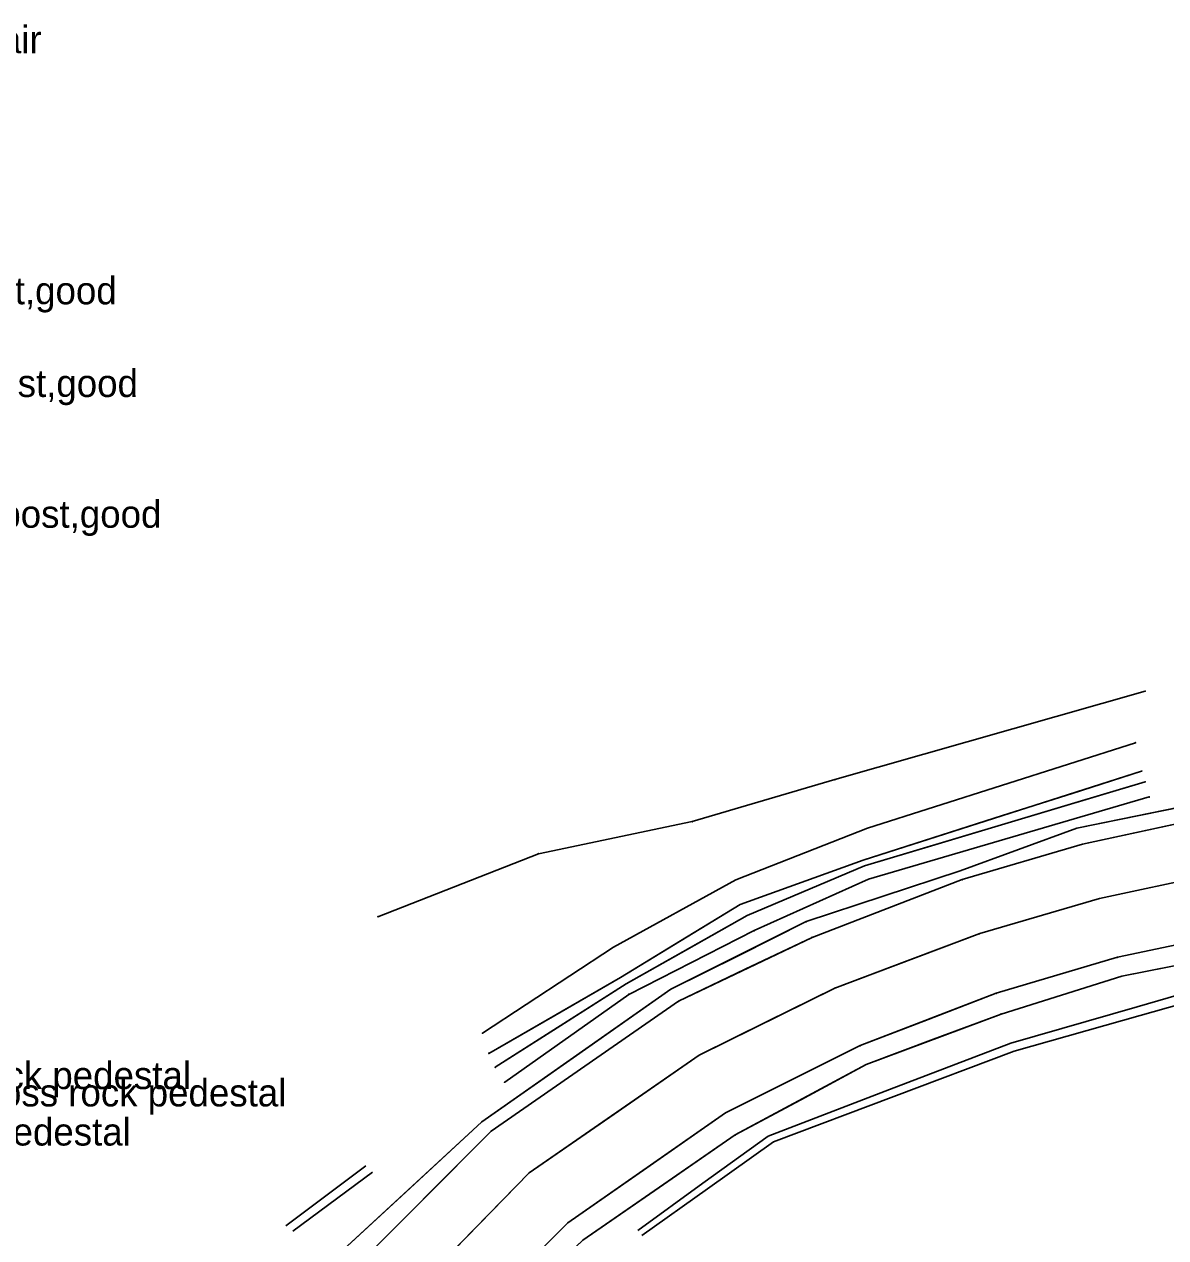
# Model space of a CAD drawing. Extents: x -99999 to 591807, y -99999 to 347168.
# Drawn here: x 591264.4 to 591472.6, y 321587.5 to 321808.7 of the extents above; entities that cross this region are included whole.
import ezdxf

# ---------------------------------------------------------------- set-up
doc = ezdxf.new("R2010")
doc.units = 0
for name, color, linetype in [('S_BREAKLINE', 7, 'Continuous'), ('S_DITCHLINE', 7, 'Continuous'), ('S_EDGE_PAVEMENT', 7, 'Continuous'), ('S_FENCE_ANNOT', 7, 'Continuous'), ('S_GRD_PT_SYM', 7, 'Continuous'), ('S_PAVEMENT_CROWN', 7, 'Continuous'), ('S_RDW_PT_SYM', 7, 'Continuous'), ('S_SHOULDER', 7, 'Continuous'), ('S_SURVEY_TEXT_ANNOT', 7, 'Continuous')]:
    doc.layers.add(name, color=color, linetype=linetype)

msp = doc.modelspace()

# ---------------------------------------------------------------- linework, layer by layer
at = {"layer": 'S_BREAKLINE'}
for points in [[(591468.8, 321687.13), (591412.23, 321671), (591386.24, 321663.34), (591358.18, 321657.49), (591328.93, 321646.02)], [(591467.04, 321677.72), (591418.2, 321662.17), (591394.18, 321652.72), (591371.88, 321640.46), (591348, 321624.79)], [(591469.54, 321667.85), (591418.4, 321652.88), (591397.51, 321643.48), (591374.67, 321631.86), (591352.04, 321615.87)]]:
    msp.add_lwpolyline(points, dxfattribs=at)
at = {"layer": 'S_DITCHLINE'}
for points in [[(591468.17, 321672.55), (591417.4, 321656.34), (591394.97, 321648.25), (591373.17, 321634.92), (591349.14, 321621.11)], [(591468.17, 321672.55), (591455.48, 321668.5), (591442.78, 321664.44), (591430.09, 321660.39), (591417.4, 321656.34), (591394.97, 321648.25), (591384.07, 321641.59), (591373.17, 321634.92), (591361.15, 321628.02), (591349.14, 321621.11)], [(591468.8, 321670.6), (591417.66, 321655.29), (591396.22, 321646.24), (591374.16, 321633.77), (591350.33, 321618.57)], [(591468.8, 321670.6), (591456.01, 321666.78), (591443.23, 321662.95), (591430.44, 321659.12), (591417.66, 321655.29), (591396.22, 321646.24), (591385.19, 321640), (591374.16, 321633.77), (591362.25, 321626.17), (591350.33, 321618.57)], [(591620.59, 321648.39), (591601.9, 321647.32), (591583.22, 321646.25), (591564.54, 321645.18), (591545.85, 321644.11), (591531.99, 321642.15), (591518.12, 321640.19), (591504.25, 321638.23), (591490.39, 321636.27), (591467.34, 321629.61), (591444.3, 321622.96), (591422.18, 321614.5), (591400.07, 321606.03), (591388.18, 321597.43), (591376.3, 321588.82)], [(591605.48, 321641.57), (591590.53, 321641.68), (591575.58, 321641.79), (591560.63, 321641.91), (591545.68, 321642.02), (591532, 321640.14), (591518.31, 321638.26), (591504.63, 321636.38), (591490.94, 321634.5), (591467.93, 321628.01), (591444.92, 321621.52), (591422.97, 321613.24), (591401.03, 321604.97), (591389.04, 321596.44), (591377.05, 321587.9)], [(591312.11, 321589.68), (591326.71, 321600.59)], [(591313.38, 321588.7), (591327.91, 321599.47)]]:
    msp.add_lwpolyline(points, dxfattribs=at)
at = {"layer": 'S_EDGE_PAVEMENT'}
for points in [[(591265.83, 321431.03), (591274.57, 321469.53), (591285.68, 321510.83), (591303.4, 321551.75), (591324.73, 321582.05), (591349.57, 321606.91), (591383.71, 321630.61), (591408.09, 321642.24), (591435.47, 321652.78), (591457.41, 321659.24), (591499.52, 321668.33), (591535.47, 321673.26), (591580.66, 321677.52), (591617.82, 321679.86), (591660.43, 321681.8), (591716.05, 321683.42)], [(591265.83, 321431.03), (591270.2, 321450.28), (591274.57, 321469.53), (591280.13, 321490.18), (591285.68, 321510.83), (591294.54, 321531.29), (591303.4, 321551.75), (591314.06, 321566.9), (591324.73, 321582.05), (591337.15, 321594.48), (591349.57, 321606.91), (591366.64, 321618.76), (591383.71, 321630.61), (591395.9, 321636.43), (591408.09, 321642.24), (591421.78, 321647.51), (591435.47, 321652.78), (591457.41, 321659.24), (591478.46, 321663.78)], [(591284.27, 321341.23), (591285.36, 321368.86), (591287.64, 321404.72), (591289.71, 321427.44), (591295.82, 321464.74), (591306.84, 321503.71), (591322.94, 321541.59), (591339.23, 321566.07), (591363.58, 321590.23), (591392.3, 321610.26), (591416.84, 321622.53), (591441.66, 321632.07), (591463.77, 321638.62), (591501.91, 321646.69), (591536.38, 321651.55), (591579.84, 321655.46), (591619.52, 321658.01), (591661.35, 321660.14), (591715.94, 321661.78)], [(591284.27, 321341.23), (591284.81, 321355.05), (591285.36, 321368.86), (591286.5, 321386.79), (591287.64, 321404.72), (591289.71, 321427.44), (591292.77, 321446.09), (591295.82, 321464.74), (591301.33, 321484.23), (591306.84, 321503.71), (591314.89, 321522.65), (591322.94, 321541.59), (591331.09, 321553.83), (591339.23, 321566.07), (591351.4, 321578.15), (591363.58, 321590.23), (591377.94, 321600.25), (591392.3, 321610.26), (591404.57, 321616.39), (591416.84, 321622.53), (591429.25, 321627.3), (591441.66, 321632.07), (591463.77, 321638.62), (591482.84, 321642.65)]]:
    msp.add_lwpolyline(points, dxfattribs=at)
at = {"layer": 'S_GRD_PT_SYM'}
for points in [[(591468.8, 321687.13), (591468.81, 321687.08), (591468.8, 321687.13), (591468.85, 321687.14), (591468.8, 321687.13), (591468.79, 321687.18), (591468.8, 321687.13), (591468.75, 321687.12)], [(591467.04, 321677.72), (591467.06, 321677.67), (591467.04, 321677.72), (591467.09, 321677.74), (591467.04, 321677.72), (591467.03, 321677.77), (591467.04, 321677.72), (591467, 321677.71)], [(591468.17, 321672.55), (591468.19, 321672.5), (591468.17, 321672.55), (591468.22, 321672.56), (591468.17, 321672.55), (591468.15, 321672.6), (591468.17, 321672.55), (591468.12, 321672.53)], [(591412.23, 321671), (591412.25, 321670.95), (591412.23, 321671), (591412.28, 321671.01), (591412.23, 321671), (591412.22, 321671.04), (591412.23, 321671), (591412.18, 321670.98)], [(591468.8, 321670.6), (591468.81, 321670.55), (591468.8, 321670.6), (591468.85, 321670.62), (591468.8, 321670.6), (591468.78, 321670.65), (591468.8, 321670.6), (591468.75, 321670.59)], [(591469.54, 321667.85), (591469.56, 321667.8), (591469.54, 321667.85), (591469.59, 321667.86), (591469.54, 321667.85), (591469.53, 321667.9), (591469.54, 321667.85), (591469.49, 321667.83)], [(591386.24, 321663.34), (591386.25, 321663.29), (591386.24, 321663.34), (591386.29, 321663.35), (591386.24, 321663.34), (591386.23, 321663.39), (591386.24, 321663.34), (591386.19, 321663.33)], [(591418.2, 321662.17), (591418.22, 321662.12), (591418.2, 321662.17), (591418.25, 321662.19), (591418.2, 321662.17), (591418.18, 321662.21), (591418.2, 321662.17), (591418.15, 321662.15)], [(591358.18, 321657.49), (591358.2, 321657.45), (591358.18, 321657.49), (591358.23, 321657.51), (591358.18, 321657.49), (591358.16, 321657.54), (591358.18, 321657.49), (591358.14, 321657.47)], [(591417.4, 321656.34), (591417.41, 321656.29), (591417.4, 321656.34), (591417.44, 321656.35), (591417.4, 321656.34), (591417.38, 321656.38), (591417.4, 321656.34), (591417.35, 321656.32)], [(591417.66, 321655.29), (591417.68, 321655.25), (591417.66, 321655.29), (591417.7, 321655.31), (591417.66, 321655.29), (591417.64, 321655.34), (591417.66, 321655.29), (591417.61, 321655.27)], [(591394.18, 321652.72), (591394.21, 321652.68), (591394.18, 321652.72), (591394.23, 321652.75), (591394.18, 321652.72), (591394.16, 321652.77), (591394.18, 321652.72), (591394.14, 321652.7)], [(591418.4, 321652.88), (591418.42, 321652.83), (591418.4, 321652.88), (591418.44, 321652.9), (591418.4, 321652.88), (591418.37, 321652.92), (591418.4, 321652.88), (591418.35, 321652.86)], [(591394.97, 321648.25), (591395, 321648.21), (591394.97, 321648.25), (591395.02, 321648.28), (591394.97, 321648.25), (591394.95, 321648.3), (591394.97, 321648.25), (591394.93, 321648.23)], [(591328.93, 321646.02), (591328.95, 321645.97), (591328.93, 321646.02), (591328.98, 321646.03), (591328.93, 321646.02), (591328.92, 321646.06), (591328.93, 321646.02), (591328.89, 321646)], [(591396.22, 321646.24), (591396.24, 321646.2), (591396.22, 321646.24), (591396.26, 321646.26), (591396.22, 321646.24), (591396.19, 321646.28), (591396.22, 321646.24), (591396.17, 321646.21)], [(591397.51, 321643.48), (591397.53, 321643.43), (591397.51, 321643.48), (591397.55, 321643.5), (591397.51, 321643.48), (591397.49, 321643.52), (591397.51, 321643.48), (591397.46, 321643.45)], [(591371.88, 321640.46), (591371.9, 321640.41), (591371.88, 321640.46), (591371.92, 321640.48), (591371.88, 321640.46), (591371.85, 321640.5), (591371.88, 321640.46), (591371.83, 321640.43)], [(591373.17, 321634.92), (591373.2, 321634.88), (591373.17, 321634.92), (591373.21, 321634.95), (591373.17, 321634.92), (591373.15, 321634.97), (591373.17, 321634.92), (591373.13, 321634.9)], [(591374.16, 321633.77), (591374.19, 321633.73), (591374.16, 321633.77), (591374.2, 321633.8), (591374.16, 321633.77), (591374.13, 321633.81), (591374.16, 321633.77), (591374.12, 321633.74)], [(591374.67, 321631.86), (591374.7, 321631.82), (591374.67, 321631.86), (591374.71, 321631.88), (591374.67, 321631.86), (591374.64, 321631.9), (591374.67, 321631.86), (591374.63, 321631.83)], [(591348, 321624.79), (591348.03, 321624.75), (591348, 321624.79), (591348.04, 321624.82), (591348, 321624.79), (591347.97, 321624.83), (591348, 321624.79), (591347.96, 321624.76)], [(591349.14, 321621.11), (591349.16, 321621.07), (591349.14, 321621.11), (591349.18, 321621.14), (591349.14, 321621.11), (591349.11, 321621.15), (591349.14, 321621.11), (591349.1, 321621.09)], [(591350.33, 321618.57), (591350.36, 321618.52), (591350.33, 321618.57), (591350.37, 321618.59), (591350.33, 321618.57), (591350.31, 321618.61), (591350.33, 321618.57), (591350.29, 321618.54)], [(591352.04, 321615.87), (591352.07, 321615.82), (591352.04, 321615.87), (591352.08, 321615.89), (591352.04, 321615.87), (591352.01, 321615.91), (591352.04, 321615.87), (591352, 321615.84)]]:
    msp.add_lwpolyline(points, close=True, dxfattribs=at)
at = {"layer": 'S_PAVEMENT_CROWN'}
for points in [[(591273.09, 321336.11), (591274.57, 321369.52), (591276.45, 321407.87), (591278.42, 321428.53), (591284.72, 321467.31), (591295.64, 321507.96), (591312.94, 321546.95), (591329.16, 321571.32), (591356.48, 321599.33), (591387.51, 321620.77), (591412.26, 321633.01), (591438.64, 321642.94), (591460.49, 321649.34), (591500.26, 321657.86), (591536.84, 321663), (591581.11, 321666.95), (591618.78, 321669.22), (591660.89, 321671.3), (591716.05, 321672.97)], [(591273.09, 321336.11), (591273.83, 321352.81), (591274.57, 321369.52), (591275.51, 321388.69), (591276.45, 321407.87), (591278.42, 321428.53), (591281.57, 321447.92), (591284.72, 321467.31), (591290.18, 321487.63), (591295.64, 321507.96), (591304.29, 321527.45), (591312.94, 321546.95), (591321.05, 321559.13), (591329.16, 321571.32), (591342.82, 321585.32), (591356.48, 321599.33), (591372, 321610.05), (591387.51, 321620.77), (591399.89, 321626.89), (591412.26, 321633.01), (591425.45, 321637.98), (591438.64, 321642.94), (591460.49, 321649.34), (591480.37, 321653.6)]]:
    msp.add_lwpolyline(points, dxfattribs=at)
at = {"layer": 'S_RDW_PT_SYM'}
for points in [[(591456.36, 321662.16), (591456.35, 321662.21), (591456.36, 321662.16), (591456.31, 321662.15), (591456.36, 321662.16), (591456.37, 321662.11), (591456.36, 321662.16), (591456.41, 321662.17)], [(591457.41, 321659.24), (591457.4, 321659.28), (591457.41, 321659.24), (591457.36, 321659.23), (591457.41, 321659.24), (591457.42, 321659.19), (591457.41, 321659.24), (591457.46, 321659.25)], [(591435.07, 321654.38), (591435.05, 321654.43), (591435.07, 321654.38), (591435.02, 321654.37), (591435.07, 321654.38), (591435.09, 321654.34), (591435.07, 321654.38), (591435.12, 321654.4)], [(591435.47, 321652.78), (591435.45, 321652.83), (591435.47, 321652.78), (591435.42, 321652.76), (591435.47, 321652.78), (591435.48, 321652.73), (591435.47, 321652.78), (591435.52, 321652.79)], [(591460.49, 321649.34), (591460.48, 321649.38), (591460.49, 321649.34), (591460.44, 321649.32), (591460.49, 321649.34), (591460.5, 321649.29), (591460.49, 321649.34), (591460.54, 321649.35)], [(591407.03, 321645.12), (591407.01, 321645.17), (591407.03, 321645.12), (591406.98, 321645.11), (591407.03, 321645.12), (591407.05, 321645.08), (591407.03, 321645.12), (591407.08, 321645.14)], [(591408.09, 321642.24), (591408.08, 321642.29), (591408.09, 321642.24), (591408.05, 321642.23), (591408.09, 321642.24), (591408.11, 321642.2), (591408.09, 321642.24), (591408.14, 321642.26)], [(591438.64, 321642.94), (591438.63, 321642.99), (591438.64, 321642.94), (591438.6, 321642.93), (591438.64, 321642.94), (591438.66, 321642.89), (591438.64, 321642.94), (591438.69, 321642.95)], [(591463.77, 321638.62), (591463.76, 321638.67), (591463.77, 321638.62), (591463.72, 321638.61), (591463.77, 321638.62), (591463.78, 321638.57), (591463.77, 321638.62), (591463.82, 321638.63)], [(591464.57, 321635.19), (591464.56, 321635.23), (591464.57, 321635.19), (591464.52, 321635.18), (591464.57, 321635.19), (591464.58, 321635.14), (591464.57, 321635.19), (591464.62, 321635.19)], [(591382.36, 321632.81), (591382.34, 321632.85), (591382.36, 321632.81), (591382.32, 321632.79), (591382.36, 321632.81), (591382.39, 321632.76), (591382.36, 321632.81), (591382.41, 321632.83)], [(591412.26, 321633.01), (591412.24, 321633.06), (591412.26, 321633.01), (591412.21, 321633), (591412.26, 321633.01), (591412.28, 321632.97), (591412.26, 321633.01), (591412.31, 321633.03)], [(591441.66, 321632.07), (591441.64, 321632.12), (591441.66, 321632.07), (591441.61, 321632.05), (591441.66, 321632.07), (591441.67, 321632.02), (591441.66, 321632.07), (591441.71, 321632.08)], [(591383.71, 321630.61), (591383.69, 321630.65), (591383.71, 321630.61), (591383.67, 321630.59), (591383.71, 321630.61), (591383.73, 321630.56), (591383.71, 321630.61), (591383.76, 321630.63)], [(591442.53, 321628.28), (591442.52, 321628.33), (591442.53, 321628.28), (591442.49, 321628.26), (591442.53, 321628.28), (591442.55, 321628.23), (591442.53, 321628.28), (591442.58, 321628.29)], [(591416.84, 321622.53), (591416.82, 321622.57), (591416.84, 321622.53), (591416.8, 321622.51), (591416.84, 321622.53), (591416.86, 321622.48), (591416.84, 321622.53), (591416.89, 321622.55)], [(591387.51, 321620.77), (591387.49, 321620.82), (591387.51, 321620.77), (591387.47, 321620.75), (591387.51, 321620.77), (591387.53, 321620.73), (591387.51, 321620.77), (591387.56, 321620.79)], [(591417.96, 321619.1), (591417.94, 321619.14), (591417.96, 321619.1), (591417.91, 321619.08), (591417.96, 321619.1), (591417.97, 321619.05), (591417.96, 321619.1), (591418, 321619.12)], [(591392.3, 321610.26), (591392.27, 321610.31), (591392.3, 321610.26), (591392.25, 321610.24), (591392.3, 321610.26), (591392.32, 321610.22), (591392.3, 321610.26), (591392.34, 321610.28)], [(591347.89, 321608.66), (591347.87, 321608.7), (591347.89, 321608.66), (591347.85, 321608.63), (591347.89, 321608.66), (591347.92, 321608.62), (591347.89, 321608.66), (591347.94, 321608.69)], [(591349.57, 321606.91), (591349.54, 321606.96), (591349.57, 321606.91), (591349.53, 321606.89), (591349.57, 321606.91), (591349.6, 321606.87), (591349.57, 321606.91), (591349.61, 321606.94)], [(591394.06, 321606.24), (591394.04, 321606.29), (591394.06, 321606.24), (591394.02, 321606.22), (591394.06, 321606.24), (591394.09, 321606.2), (591394.06, 321606.24), (591394.11, 321606.26)], [(591356.48, 321599.33), (591356.45, 321599.37), (591356.48, 321599.33), (591356.44, 321599.3), (591356.48, 321599.33), (591356.51, 321599.29), (591356.48, 321599.33), (591356.52, 321599.36)], [(591363.58, 321590.23), (591363.55, 321590.27), (591363.58, 321590.23), (591363.53, 321590.2), (591363.58, 321590.23), (591363.6, 321590.19), (591363.58, 321590.23), (591363.62, 321590.26)]]:
    msp.add_lwpolyline(points, close=True, dxfattribs=at)
at = {"layer": 'S_SHOULDER'}
for points in [[(591264.76, 321431.46), (591270.73, 321470.65), (591281.62, 321511.98), (591300.21, 321554.03), (591321.75, 321584.49), (591347.89, 321608.66), (591382.36, 321632.81), (591407.03, 321645.12), (591435.07, 321654.38), (591456.36, 321662.16), (591499.13, 321670.85), (591534.55, 321676.66), (591580.75, 321679.7), (591617.67, 321682.67), (591660.33, 321683.79), (591716.05, 321685.24)], [(591264.76, 321431.46), (591267.74, 321451.06), (591270.73, 321470.65), (591276.18, 321491.32), (591281.62, 321511.98), (591290.91, 321533.01), (591300.21, 321554.03), (591310.98, 321569.26), (591321.75, 321584.49), (591334.82, 321596.57), (591347.89, 321608.66), (591365.13, 321620.73), (591382.36, 321632.81), (591394.7, 321638.97), (591407.03, 321645.12), (591421.05, 321649.75), (591435.07, 321654.38), (591456.36, 321662.16), (591477.74, 321666.51)], [(591286.25, 321341.03), (591286.96, 321368.53), (591288.65, 321404.58), (591291.29, 321427.17), (591299, 321463.91), (591309.64, 321503.38), (591326.52, 321539.51), (591346.22, 321567.94), (591366.31, 321587.07), (591394.06, 321606.24), (591417.96, 321619.1), (591442.53, 321628.28), (591464.57, 321635.19), (591502.76, 321642.72), (591536.98, 321647.91), (591580.11, 321651.49), (591619.15, 321654.09), (591661.92, 321656.35), (591716.12, 321658.87)], [(591286.25, 321341.03), (591286.61, 321354.78), (591286.96, 321368.53), (591287.8, 321386.56), (591288.65, 321404.58), (591291.29, 321427.17), (591295.15, 321445.54), (591299, 321463.91), (591304.32, 321483.65), (591309.64, 321503.38), (591318.08, 321521.45), (591326.52, 321539.51), (591336.37, 321553.73), (591346.22, 321567.94), (591356.26, 321577.51), (591366.31, 321587.07), (591380.19, 321596.66), (591394.06, 321606.24), (591406.01, 321612.67), (591417.96, 321619.1), (591430.24, 321623.69), (591442.53, 321628.28), (591464.57, 321635.19), (591483.67, 321638.95)]]:
    msp.add_lwpolyline(points, dxfattribs=at)

# ---------------------------------------------------------------- texts
at = {"layer": 'S_FENCE_ANNOT'}
for s, p in [('5 strand brb st post,fair', (591199.24, 321803.4)), ('5strand brb st post,good', (591209.19, 321757.63)), ('5strand brb st post,good', (591213.06, 321740.74)), ('5strand brb st post,good', (591217.34, 321716.91))]:
    msp.add_text(s, height=5, dxfattribs=at).set_placement(p)
at = {"layer": 'S_SURVEY_TEXT_ANNOT'}
for p in [(591216.8, 321614.6), (591234.19, 321611.44), (591205.83, 321604.31)]:
    msp.add_text('decor. cross rock pedestal', height=5, dxfattribs=at).set_placement(p)

doc.saveas('drawing.dxf')
